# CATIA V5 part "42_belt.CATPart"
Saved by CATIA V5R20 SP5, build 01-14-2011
Part number: 42_belt
Bounding box of the stored display mesh (mm): x -25 to 25, y 21.362 to 165.313, z -172.5 to -157.5
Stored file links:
  C:\Documents and Settings\anizard\Bureau\13\42_belt.CATPart
  C:\Documents and Settings\anizard\Bureau\13\anizard.CATProduct
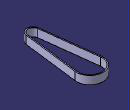
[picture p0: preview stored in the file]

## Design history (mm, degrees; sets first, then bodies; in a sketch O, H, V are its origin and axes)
External parameters (linked from other documents)
  External.diam_ext = 46 mm
  External.diametre_36 = 20 mm
Set1
  Plane1: linked copy from another document
  Point1: linked copy from another document
  Point2: linked copy from another document
  Plane2: linked copy from another document
  Point3: linked copy from another document
  Point4: linked copy from another document
Body1 (main body)
  Sketch1 on Plane1, origin (0, 0, -157.5), H (1, 0, 0), V (0, -1, 0)
    line L1 (22.8296, -137.5676) -> (9.9259, -32.147)
    arc A1 centre (0, -33.3619) radius 10 from (9.9259, -32.147) to (-9.9259, -32.147) ccw
    line L2 (-9.9259, -32.147) -> (-22.8296, -137.5676)
    arc A2 centre (0, -140.3619) radius 23 from (-22.8296, -137.5676) to (22.8296, -137.5676) ccw
    line L3 (24.8148, -137.3246) -> (11.9111, -31.904)
    arc A3 centre (0, -33.3619) radius 12 from (11.9111, -31.904) to (-11.9111, -31.904) ccw
    point P9 (0, -33.3619)
    line L4 (-11.9111, -31.904) -> (-24.8148, -137.3246)
    arc A4 centre (0, -140.3619) radius 25 from (-24.8148, -137.3246) to (24.8148, -137.3246) ccw
    point P12 (0, -140.3619)
    reference projected point E1 (0, -33.3619) from Point1
    reference projected point E2 (0, -140.3619) from Point2
    construction circle A5 centre (0, -33.3619) radius 10
    reference projected point E3 (0, -43.3619) from Point3
    reference projected point E4 (0, -163.3619) from Point4
    distance L2 L4 = 2
    tangency: A1 L1, L2 A1, A2 L2, L1 A2, A3 L3, L4 A3, A4 L4, A4 L3, A1 A5
    concentricity: A4 A2, A3 A1, A5 A1
    parallelism: L3 L1
    coincidence: P9 E1, P12 E2, A5 E3, A2 E4
  Pad1: profile Sketch1, direction (0, 0, -1), up to Plane2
